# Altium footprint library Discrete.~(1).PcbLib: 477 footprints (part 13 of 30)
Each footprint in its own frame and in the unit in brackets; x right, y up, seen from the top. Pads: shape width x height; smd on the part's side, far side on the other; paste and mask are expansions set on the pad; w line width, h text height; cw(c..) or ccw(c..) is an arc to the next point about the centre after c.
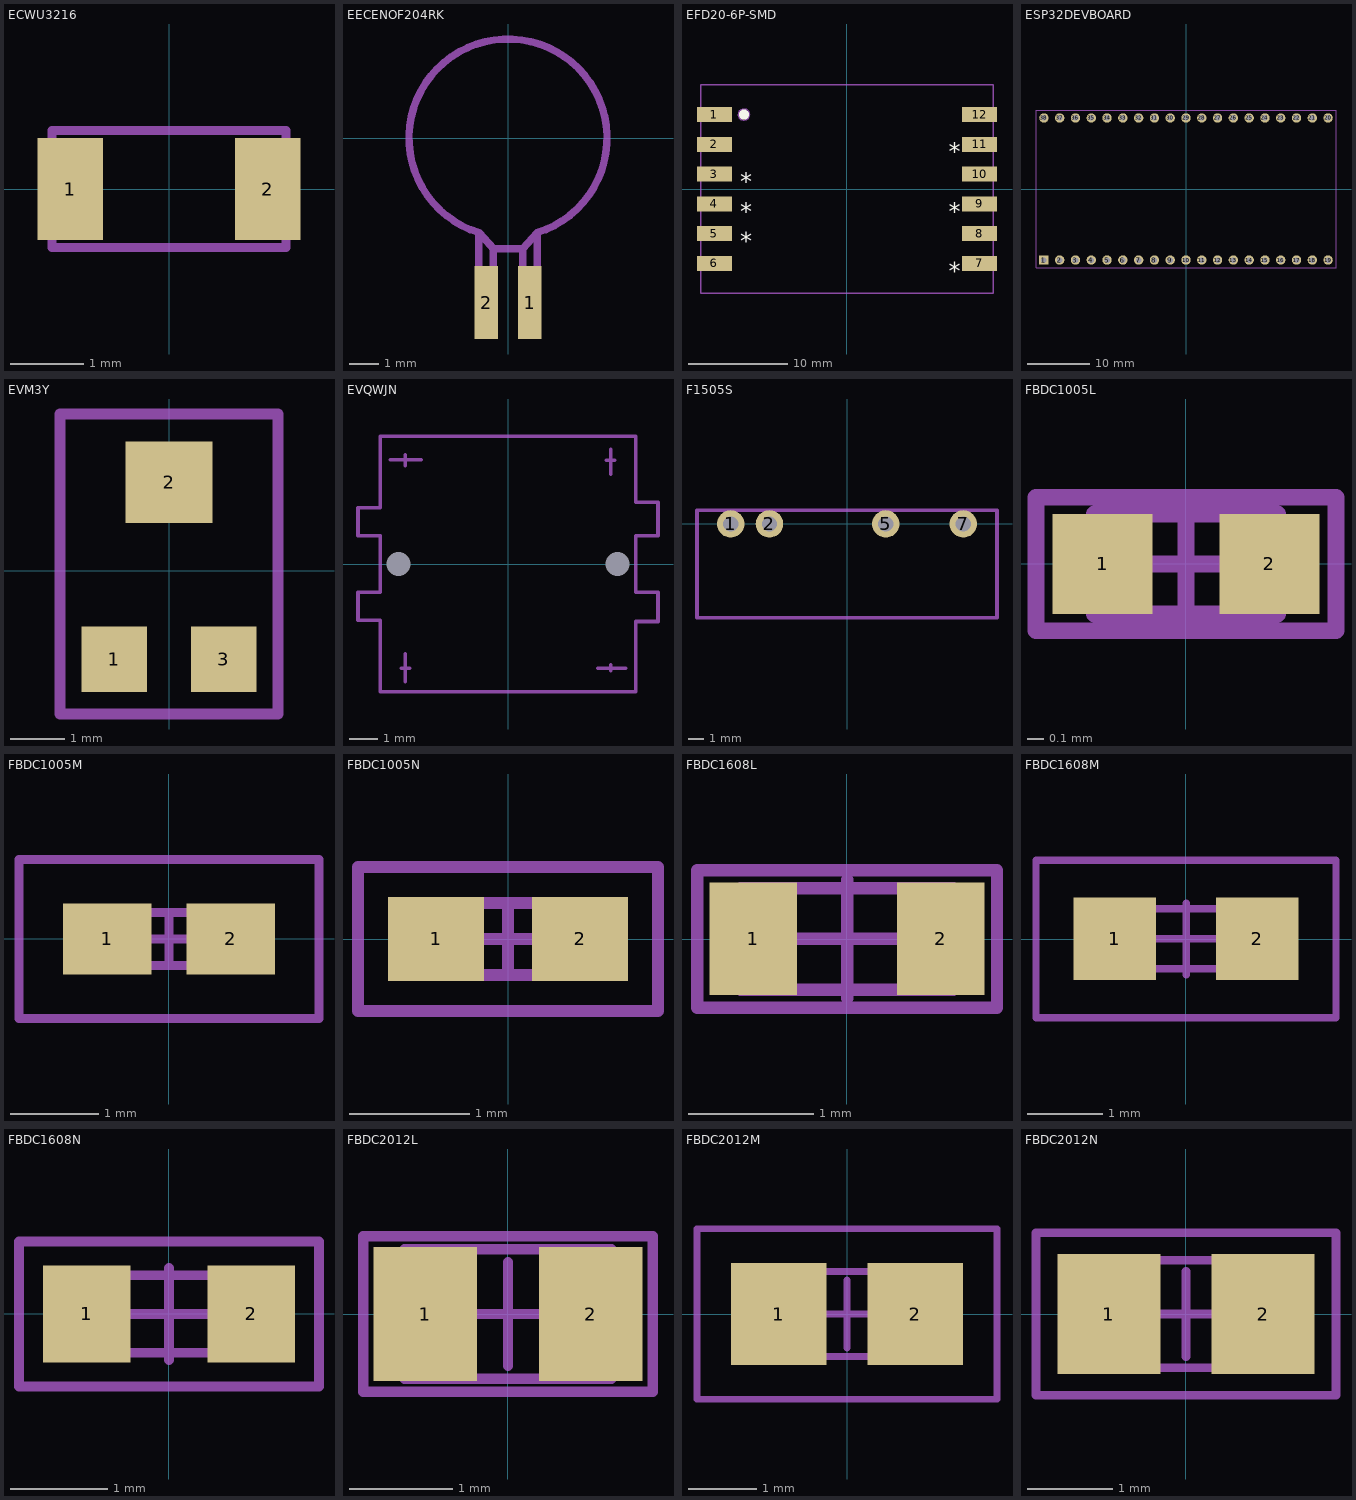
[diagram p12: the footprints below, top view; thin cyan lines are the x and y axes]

## ECWU3216 [mm]
height 0.9
pads (2):
  rect 0.9x1.4 smd: 1(-1.35,0) 2(1.35,0)
Mechanical 13:
  lines w0.127: -1.6,-0.8 -1.6,0.8 1.6,0.8 1.6,-0.8 -1.6,-0.8
3D body: height 0.9, standoff 0, extent -1.6,-0.8 1.6,0.8

## EECENOF204RK [mm]
pads (2):
  rect 0.8x2.5 smd: 1(0.75,-5.65) 2(-0.75,-5.65)
Mechanical 13:
  lines w0.254: -1,-3.275 -1,-6.6 -0.5,-6.6 -0.5,-3.8 ; -0.5,-3.8 -0.993,-3.252 cw(c0,0) 1,-3.25 ; -0.5,-3.8 0.5,-3.8 ; 0.5,-3.8 0.5,-6.6 1,-6.6 1,-3.25 ; 0.5,-3.8 1,-3.25
3D body: height 1.8, standoff 0, extent -3.373,-3.393 3.4,3.393
3D body: height 0.4, standoff 0, extent -1,-6.6 -0.5,-3.275
3D body: height 0.4, standoff 0, extent 0.5,-6.6 1,-3.25
3D body: height 1.8, standoff 0, extent -0.993,-3.8 1,-3.25

## EFD20-6P-SMD [mm]
pads (12):
  rect 3.515x1.52 smd: 1(-13.357,7.5) 2(-13.357,4.5) 3(-13.357,1.5) 4(-13.357,-1.5) 5(-13.357,-4.5) 6(-13.357,-7.5) 7(13.358,-7.5) 8(13.358,-4.5) 9(13.358,-1.5) 10(13.358,1.5) 11(13.358,4.5) 12(13.358,7.5)
Top Overlay:
  circle w0.508: c-10.381,7.5 r0.25
  text "*" at 10.25,6 h3
  text "*" at 10.25,0 h3
  text "*" at 10.25,-6 h3
  text "*" at -10.75,-3 h3
  text "*" at -10.75,0 h3
  text "*" at -10.75,3 h3
Mechanical 13:
  circle w0.127: c-10.381,7.5 r0.559
  lines w0.127: -14.75,-10.5 -14.75,10.5 14.75,10.5 14.75,-10.5 -14.75,-10.5
3D body "45841.stp": height 10.85, standoff 0.05, extent -14.75,-10.5 14.75,10.5

## ESP32DEVBOARD [mm]
pads (38):
  rect 1.5x1.5 hole 0.9: 1(-22.86,-11.43)
  round 1.5 hole 0.9: 2(-20.32,-11.43) 3(-17.78,-11.43) 4(-15.24,-11.43) 5(-12.7,-11.43) 6(-10.16,-11.43) 7(-7.62,-11.43) 8(-5.08,-11.43) 9(-2.54,-11.43) 10(0,-11.43) 11(2.54,-11.43) 12(5.08,-11.43) 13(7.62,-11.43) 14(10.16,-11.43) 15(12.7,-11.43) 16(15.24,-11.43) 17(17.78,-11.43) 18(20.32,-11.43) 19(22.86,-11.43) 20(22.86,11.43) 21(20.32,11.43) 22(17.78,11.43) 23(15.24,11.43) 24(12.7,11.43) 25(10.16,11.43) 26(7.62,11.43) 27(5.08,11.43) 28(2.54,11.43) 29(0,11.43) 30(-2.54,11.43) 31(-5.08,11.43) 32(-7.62,11.43) 33(-10.16,11.43) 34(-12.7,11.43) 35(-15.24,11.43) 36(-17.78,11.43) 37(-20.32,11.43) 38(-22.86,11.43)
Mechanical 13:
  lines w0.152: -24.13,-12.7 -24.13,12.7 24.13,12.7 24.13,-12.7 -24.13,-12.7
3D body: height 11, standoff 10, extent -24.13,-12.7 24.13,12.7
3D body: height 11, standoff 10, extent -24.13,-12.7 24.13,12.7

## EVM3Y [mm]
pads (3):
  rect 1.2x1.2 smd: 1(-1,-1.625) 3(1,-1.625)
  rect 1.6x1.5 smd: 2(0,1.625)
Mechanical 15:
  lines w0.2: -2,-2.625 -2,2.875 2,2.875 2,-2.625 -2,-2.625
3D body "70336.stp": height 1.13, standoff -0.02, extent -1.8,-1.912 1.8,2.05

## EVQWJN [mm] "JOGBALL"
height 5
pads (2):
  round 0 hole 0.85 unplated: MH(-3.9,0)
  rect 0x0 hole 0.85 unplated: MH(3.9,0)
Mechanical 13:
  lines w0.127: -4.2,3.715 -3.1,3.715 ; -3.8,-3.715 -3.5,-3.715 ; -3.665,-4.2 -3.665,-3.2 ; -3.665,3.5 -3.665,3.9 ; 3.2,-3.715 4.2,-3.715 ; 3.5,3.7 3.8,3.7 ; 3.665,-3.8 3.665,-3.6 ; 3.665,3.2 3.665,4.1 ; -4.55,1 -5.35,1 -5.35,2 -4.55,2 -4.55,4.55 4.55,4.55 4.55,2.2 5.35,2.2 5.35,1 4.55,1 4.55,-1 5.35,-1 5.35,-2.05 4.55,-2.05 4.55,-4.55 -4.55,-4.55 -4.55,-2 -5.35,-2 -5.35,-1 -4.55,-1 -4.55,1 ; -4.55,1 -4.55,1
3D body: height 8.5, standoff 3.5, extent -2.498,-2.499 2.497,2.499
3D body: height 7, standoff 2, extent -5.35,-4.55 5.35,4.55

## F1505S [mm]
pads (4):
  round 1.8 hole 1: 1(-7.62,0) 2(-5.08,0) 5(2.54,0) 7(7.62,0)
Mechanical 13:
  lines w0.254: -9.83,-6.15 9.83,-6.15 9.83,0.9 -9.83,0.9 -9.83,-6.15
3D body: height 10.16, standoff 0, extent -9.83,-6.15 9.83,0.9

## FBDC1005L [mm] "Ferrite Bead, Body 1.1x0.5mm, IPC High Density"
height 0.4
pads (2):
  rect 0.6x0.6 smd: 1(-0.5,0) 2(0.5,0)
Mechanical 13:
  lines w0.1: -0.55,-0.3 -0.55,0.3 0.55,0.3 0.55,-0.3 -0.55,-0.3
Mechanical 15:
  lines w0.1: -0.3,0 0.3,0 ; 0,-0.3 0,0.3 ; -0.9,-0.4 -0.9,0.4 0.9,0.4 0.9,-0.4 -0.9,-0.4
3D body "User Library-FB_1005.STEP": height 0.5, standoff 0, extent -0.5,-0.25 0.5,0.25

## FBDC1005M [mm] "Ferrite Bead, Body 1.1x0.5mm, IPC Low Density"
height 0.4
pads (2):
  rect 1x0.8 smd: 1(-0.7,0) 2(0.7,0)
Mechanical 13:
  lines w0.1: -0.55,-0.3 -0.55,0.3 0.55,0.3 0.55,-0.3 -0.55,-0.3
Mechanical 15:
  lines w0.1: -0.3,0 0.3,0 ; 0,-0.3 0,0.3 ; -1.7,-0.9 -1.7,0.9 1.7,0.9 1.7,-0.9 -1.7,-0.9
3D body "User Library-FB_1005.STEP": height 0.5, standoff 0, extent -0.5,-0.25 0.5,0.25

## FBDC1005N [mm] "Ferrite Bead, Body 1.1x0.5mm, IPC Medium Density"
height 0.4
pads (2):
  rect 0.8x0.7 smd: 1(-0.6,0) 2(0.6,0)
Mechanical 13:
  lines w0.1: -0.55,-0.3 -0.55,0.3 0.55,0.3 0.55,-0.3 -0.55,-0.3
Mechanical 15:
  lines w0.1: -0.3,0 0.3,0 ; 0,-0.3 0,0.3 ; -1.25,-0.6 -1.25,0.6 1.25,0.6 1.25,-0.6 -1.25,-0.6
3D body "User Library-FB_1005.STEP": height 0.5, standoff 0, extent -0.5,-0.25 0.5,0.25

## FBDC1608L [mm] "Ferrite Bead, Body 1.6x0.8mm, IPC High Density"
height 0.6
pads (2):
  rect 0.7x0.9 smd: 1(-0.75,0) 2(0.75,0)
Mechanical 13:
  lines w0.1: -0.85,-0.406 0.85,-0.406 0.85,0.406 -0.85,0.406 -0.85,-0.406
Mechanical 15:
  lines w0.1: -0.475,0 0.475,0 ; 0,-0.475 0,0.475 ; -1.2,-0.55 1.2,-0.55 1.2,0.55 -1.2,0.55 -1.2,-0.55
3D body "User Library-FB_1608-1.STEP": height 0.8, standoff 0, extent -0.8,-0.4 0.8,0.4

## FBDC1608M [mm] "Ferrite Bead, Body 1.6x0.8mm, IPC Low Density"
height 0.6
pads (2):
  rect 1.1x1.1 smd: 1(-0.95,0) 2(0.95,0)
Mechanical 13:
  lines w0.1: -0.85,-0.4 -0.85,0.4 0.85,0.4 0.85,-0.4 -0.85,-0.4
Mechanical 15:
  lines w0.1: -0.475,0 0.475,0 ; 0,-0.475 0,0.475 ; -2,-1.05 -2,1.05 2,1.05 2,-1.05 -2,-1.05
3D body "User Library-FB_1608-1.STEP": height 0.8, standoff 0, extent -0.8,-0.4 0.8,0.4

## FBDC1608N [mm] "Ferrite Bead, Body 1.6x0.8mm, IPC Medium Density"
height 0.6
pads (2):
  rect 0.9x1 smd: 1(-0.85,0) 2(0.85,0)
Mechanical 13:
  lines w0.1: -0.85,-0.4 0.85,-0.4 0.85,0.4 -0.85,0.4 -0.85,-0.4
Mechanical 15:
  lines w0.1: -0.475,0 0.475,0 ; 0,-0.475 0,0.475 ; -1.55,-0.75 1.55,-0.75 1.55,0.75 -1.55,0.75 -1.55,-0.75
3D body "User Library-FB_1608-1.STEP": height 0.8, standoff 0, extent -0.8,-0.4 0.8,0.4

## FBDC2012L [mm] "Ferrite Bead, Body 2.0x1.3mm, IPC High Density"
height 0.65
pads (2):
  rect 1x1.3 smd: 1(-0.8,0) 2(0.8,0)
Mechanical 13:
  lines w0.1: -1,-0.625 -1,0.625 1,0.625 1,-0.625 -1,-0.625
Mechanical 15:
  lines w0.1: -0.5,0 0.5,0 ; 0,-0.5 0,0.5 ; -1.4,-0.75 -1.4,0.75 1.4,0.75 1.4,-0.75 -1.4,-0.75
3D body "User Library-FB_2012-1.STEP": height 0.85, standoff 0, extent -1,-0.625 1,0.625

## FBDC2012M [mm] "Ferrite Bead, Body 2.0x1.3mm, IPC Low Density"
height 0.65
pads (2):
  rect 1.4x1.5 smd: 1(-1,0) 2(1,0)
Mechanical 13:
  lines w0.1: -1,-0.625 -1,0.625 1,0.625 1,-0.625 -1,-0.625
Mechanical 15:
  lines w0.1: -0.5,0 0.5,0 ; 0,-0.5 0,0.5 ; -2.2,-1.25 -2.2,1.25 2.2,1.25 2.2,-1.25 -2.2,-1.25
3D body "User Library-FB_2012-1.STEP": height 0.85, standoff 0, extent -1,-0.625 1,0.625

## FBDC2012N [mm] "Ferrite Bead, Body 2.0x1.3mm, IPC Medium Density"
height 0.65
pads (2):
  rect 1.2x1.4 smd: 1(-0.9,0) 2(0.9,0)
Mechanical 13:
  lines w0.1: -1,-0.625 1,-0.625 1,0.625 -1,0.625 -1,-0.625
Mechanical 15:
  lines w0.1: -0.5,0 0.5,0 ; 0,-0.5 0,0.5 ; -1.75,-0.95 1.75,-0.95 1.75,0.95 -1.75,0.95 -1.75,-0.95
3D body "User Library-FB_2012-1.STEP": height 0.85, standoff 0, extent -1,-0.625 1,0.625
